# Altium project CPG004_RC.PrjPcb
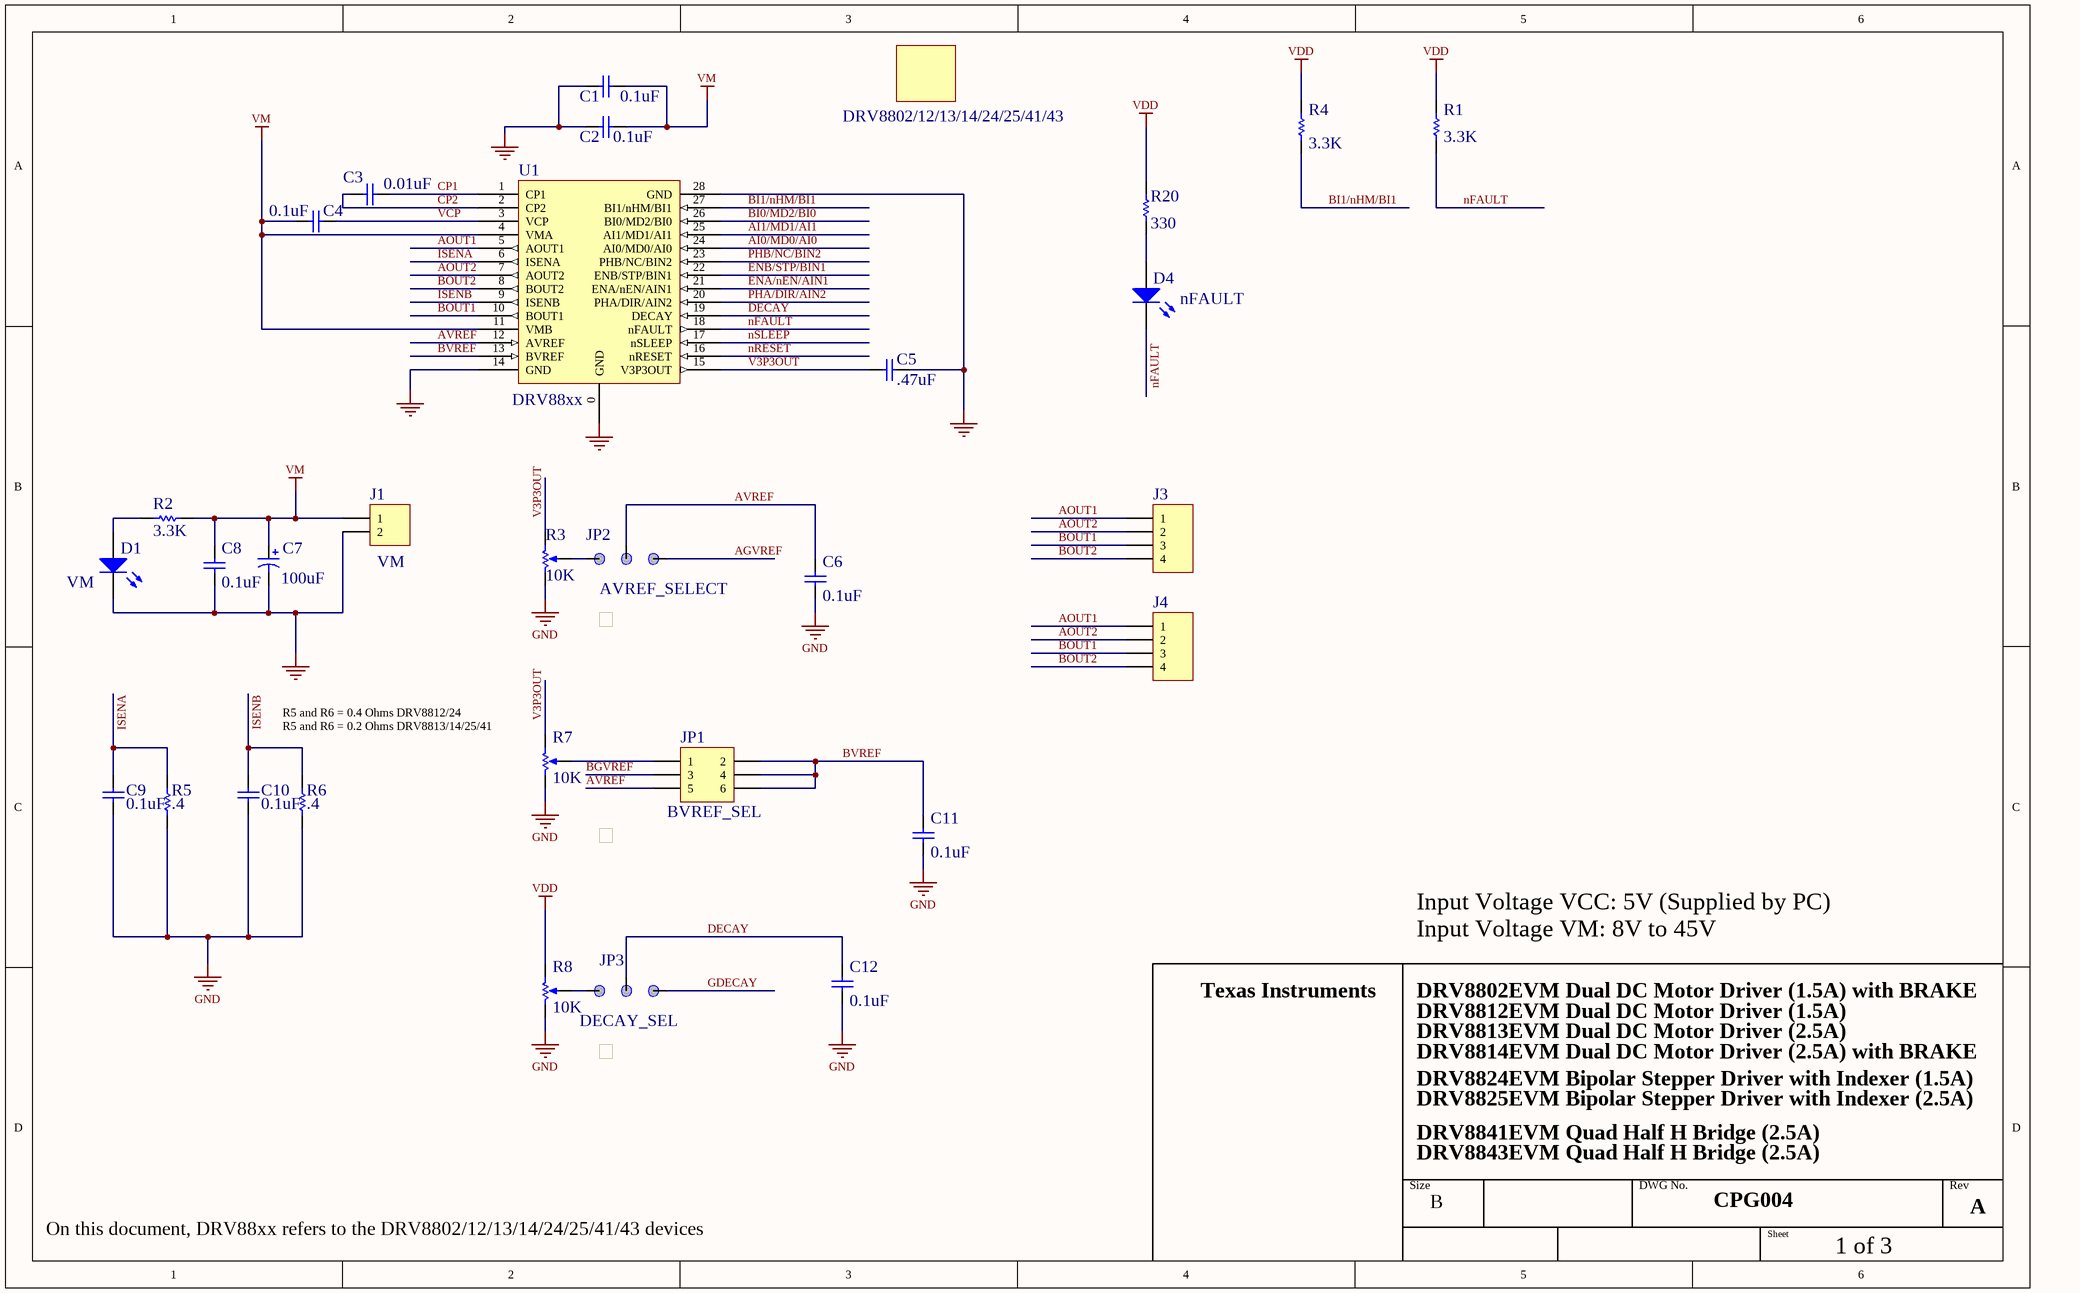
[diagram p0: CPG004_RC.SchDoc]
Title: CPG004 DRV88xx Customer Evaluation Module; ProjectFileName: CPG004 DRV8812/13/14/24/25/41 Customer EVM
3 sheets, 100 parts. Net scope: global (net labels, ports and power ports of the same name join across sheets).
Board file: CPG004_RC.PcbDoc
Sheets:
  CPG004_RC.SchDoc
  CPG004_RC_MSP430.SchDoc
  CPG004_RC_TS.SchDoc

## Sheet CPG004_RC.SchDoc: Test
size B; PageSetup: Record=PageOptions|CenterHorizontal=True|CenterVertical=True|PrintScale=0.70|XCorrection=1.00|YCorrection=1.00|PrintKind=1|BorderSize=5000000|LeftOffset=0|BottomOffset=0|Orientation=2|PaperLength=1000|PaperWidth=1000|Scale=100|PaperSource=15|PrintQuality=600|MediaType=1|DitherType=10|PaperKind=11x17|PrintScaleMode=1

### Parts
C1  value 0.1uF  [1206]
C2  value 0.1uF  [1206]
C3  0.01uF  [0805]
C4  value 0.1uF  [0805]
C5  value .47uF  [0805]
C6  value 0.1uF  [0805]
C7  value 100uF  [RB .2/.4 SS]
C8  value 0.1uF  [0805]
C9  value 0.1uF  [0805]
C10  value 0.1uF  [0805]
C11  value 0.1uF  [0805]
C12  value 0.1uF  [0805]
D1  VM  [1206_LED]
D4  nFAULT  [1206_LED]
J1  VM  [PWR_CONN2]
J3  Header 4  [PWR_CONN4]  (value not drawn)
J4  Header 4  [HDR1X4]  (value not drawn)
JP1  BVREF_SEL  [HDR2X3]
JP2  AVREF_SELECT  [JMP0.3]
JP3  DECAY_SEL  [JMP0.3]
R1  value 3.3K  [0805]
R2  value 3.3K  [0805]  (hidden comment: Res2)
R3  value 10K  [VR5]  (hidden comment: AVREF)
R4  value 3.3K  [0805]
R5  value .4  [2512]
R6  value .4  [2512]
R7  value 10K  [VR5]  (hidden comment: BVREF)
R8  value 10K  [VR5]  (hidden comment: DECAY)
R20  value 330  [0805]  (hidden comment: Res2)
SHNT1  3 pin Jumper Shunt  (value not drawn)
SHNT2  3 pin Jumper Shunt  (value not drawn)
SHNT3  3 pin Jumper Shunt  (value not drawn)
TL1  DRV8802/12/13/14/24/25/41/43  [TI LOGO]
U1  DRV88xx  [HTSSOP28 - PWP]

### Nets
GND: C1.1 C2.1 C5.1 C6.1 C7.2 C8.1 C9.1 C10.1 C11.1 C12.1 D1.2(K) J1.2 R3.3(BOT) R5.2 R6.2 R7.3(BOT) R8.3(BOT) U1.0(GND) U1.14(GND) U1.28(GND)
VDD: R1.1 R4.1 R8.1(TOP) R20.2
VM: C1.2 C2.2 C4.1 C7.1 C8.2 J1.1 R2.1 U1.4(VMA) U1.11(VMB)
AGVREF: JP2.1
AI0/MD0/AI0: U1.24(AI0/MD0/AI0)
AI1/MD1/AI1: U1.25(AI1/MD1/AI1)
AOUT1: J3.1 J4.1 U1.5(AOUT1)
AOUT2: J3.2 J4.2 U1.7(AOUT2)
AVREF: C6.2 JP1.5 JP2.2 U1.12(AVREF)
BGVREF: JP1.3
BI0/MD2/BI0: U1.26(BI0/MD2/BI0)
BI1/nHM/BI1: R4.2 U1.27(BI1/nHM/BI1)
BOUT1: J3.3 J4.3 U1.10(BOUT1)
BOUT2: J3.4 J4.4 U1.8(BOUT2)
BVREF: C11.2 JP1.2 JP1.4 JP1.6 U1.13(BVREF)
CP1: C3.1 U1.1(CP1)
CP2: C3.2 U1.2(CP2)
DECAY: C12.2 JP3.2 U1.19(DECAY)
ENA/nEN/AIN1: U1.21(ENA/nEN/AIN1)
ENB/STP/BIN1: U1.22(ENB/STP/BIN1)
GDECAY: JP3.1
ISENA: C9.2 R5.1 U1.6(ISENA)
ISENB: C10.2 R6.1 U1.9(ISENB)
nFAULT: D4.2(K) R1.2 U1.18(nFAULT)
nRESET: U1.16(nRESET)
nSLEEP: U1.17(nSLEEP)
PHA/DIR/AIN2: U1.20(PHA/DIR/AIN2)
PHB/NC/BIN2: U1.23(PHB/NC/BIN2)
V3P3OUT: C5.2 R3.1(TOP) R7.1(TOP) U1.15(V3P3OUT)
VCP: C4.2 U1.3(VCP)
NetD1_1: D1.1(A) R2.2
NetD4_1: D4.1(A) R20.1
NetJP1_1: JP1.1 R7.2(TAP)
NetJP2_3: JP2.3 R3.2(TAP)
NetJP3_3: JP3.3 R8.2(TAP)

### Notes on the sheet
- R5 and R6 = 0.4 Ohms DRV8812/24
- R5 and R6 = 0.2 Ohms DRV8813/14/25/41
- Input Voltage VCC: 5V (Supplied by PC)
- Input Voltage VM: 8V to 45V
- Texas Instruments
- DRV8812EVM Dual DC Motor Driver (1.5A)
- DRV8813EVM Dual DC Motor Driver (2.5A)
- DRV8802EVM Dual DC Motor Driver (1.5A) with BRAKE
- DRV8814EVM Dual DC Motor Driver (2.5A) with BRAKE
- DRV8824EVM Bipolar Stepper Driver with Indexer (1.5A)
- DRV8825EVM Bipolar Stepper Driver with Indexer (2.5A)
- DRV8841EVM Quad Half H Bridge (2.5A)
- DRV8843EVM Quad Half H Bridge (2.5A)
- On this document, DRV88xx refers to the DRV8802/12/13/14/24/25/41/43 devices
- Size
- B
- DWG No.
- CPG004
- Sheet
- Rev
- A
- 1 of 3

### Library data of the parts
C1 C2 = Cap: CAP .10UF 50V CERAMIC X7R 1206; Manufacturer: Kemet; Part #: 399-1248-1-ND; MFG Part Number: C1206C104M5RACTU
C3 = Cap: CAP 10000PF 50V CERAMIC X7R 0805; Manufacturer: Kemet; Part #: 399-1158-1-ND; MFG Part Number: C0805C103K5RACTU; Value: .01uF
C4 C6 C8-C12 = Cap: CAP .10UF 50V CERAMIC X7R 0805; Manufacturer: Kemet; Part #: 399-1170-1-ND; MFG Part Number: C0805C104K5RACTU
C5 = Cap: CAP CER .47UF 25V X7R 0805 FO; Manufacturer: Kemet; Part #: 399-5112-1-ND; MFG Part Number: C0805F474K3RACTU
C7 = Cap Pol1: CAP 100UF 50V ELECT M RADIAL; Part #: P5182-ND; MFG Part Number: ECA-1HM101; Manufacturer: Panasonic
D1 D4 = LED3: LED RED CLEAR 1206 SMD; MFG Part Number: HBR1105W-TR; Manufacturer: Stanley Electric & Co; Part #: 404-1033-1-ND; Value: LED RED
J1 = Header 2: TERM BLOCK 5.08MM VERT 2POS PCB; MFG Part Number: OSTTA024163; Manufacturer: On Shore Technologies; Part #: ED2580-ND; Value: Connector
J3 = Header 4: TERM BLOCK 5.08MM VERT 4POS PCB; Manufacturer: On Shore Technologies; MFG Part Number: OSTTA044163; Part #: ED2582-ND
J4 = Header 4: CONN HEADER .100 SNGL STR 4POS; Manufacturer: 3M; MFG Part Number: 929647-09-04-I; Part #: 929647-09-04-ND; Value: 4 Pos Header
JP1 = Header 3X2: CONN HEADER .100 DUAL STR 6POS; Manufacturer: 3M; MFG Part Number: 929665-09-03-I; Part #: 929665-09-03-ND; Value: 6 Pos Dual Header
JP2 JP3 = JUMPER 3 PIN: CONN HEADER .100 SINGL STR 3POS; Manufacturer: 3M; MFG Part Number: 929647-09-03-I; Part #: 929647-09-03-ND; VALUE: 3 Pos Header
R1 R4 = Res1: RES 3.3K OHM 1/8W 5% 0805 SMD; Manufacturer: Yageo; Part #: 311-3.3KARCT-ND; MFG Part Number: RC0805JR-073K3L
R2 = Res2: RES 3.3K OHM 1/8W 5% 0805 SMD; MFG Part Number: RC0805JR-073K3L; Manufacturer: Yageo; Part #: 311-3.3KARCT-ND
R3 R7 R8 = RPot: TRIMPOT CERM 10K OHM 12TRN TOP; Part #: 490-3008-ND; Manufacturer: Murata; MFG Part Number: PV37Y103C01B00
R5 R6 = Res1: RES .4OHM 2W 1% 2512 SMD; Manufacturer: Stackpole; Part #: CSRN2512FKR400CT-ND; MFG Part Number: CSRN2512FKR400
R20 = Res2: RES 330 OHM 1/8W 5% 0805 SMD; MFG Part Number: RC0805JR-07330RL; Manufacturer: Yageo; Part #: 311-330ARCT-ND
SHNT1-SHNT3 = ShuntJumper: CONN SHUNT; Manufacturer: Samtec; MFG Part Number: SNT-100-BK-T-H; Part #: SNT-100-BK-T-H-ND
TL1 = TI_LOGO: CPG004 Bare Board; Manufacturer: Texas Instruments; MFG Part Number: DRV88xx Customer EVM Bare Board; Part #: DRV8812 Customer EVM Bare Board; Value: PCB
U1 = Io_Europa: Stepper / DC Motor Driver; Manufacturer: Texas Instruments

## Sheet CPG004_RC_MSP430.SchDoc: CPG004 DRV88xx Customer Evaluation Module
size B
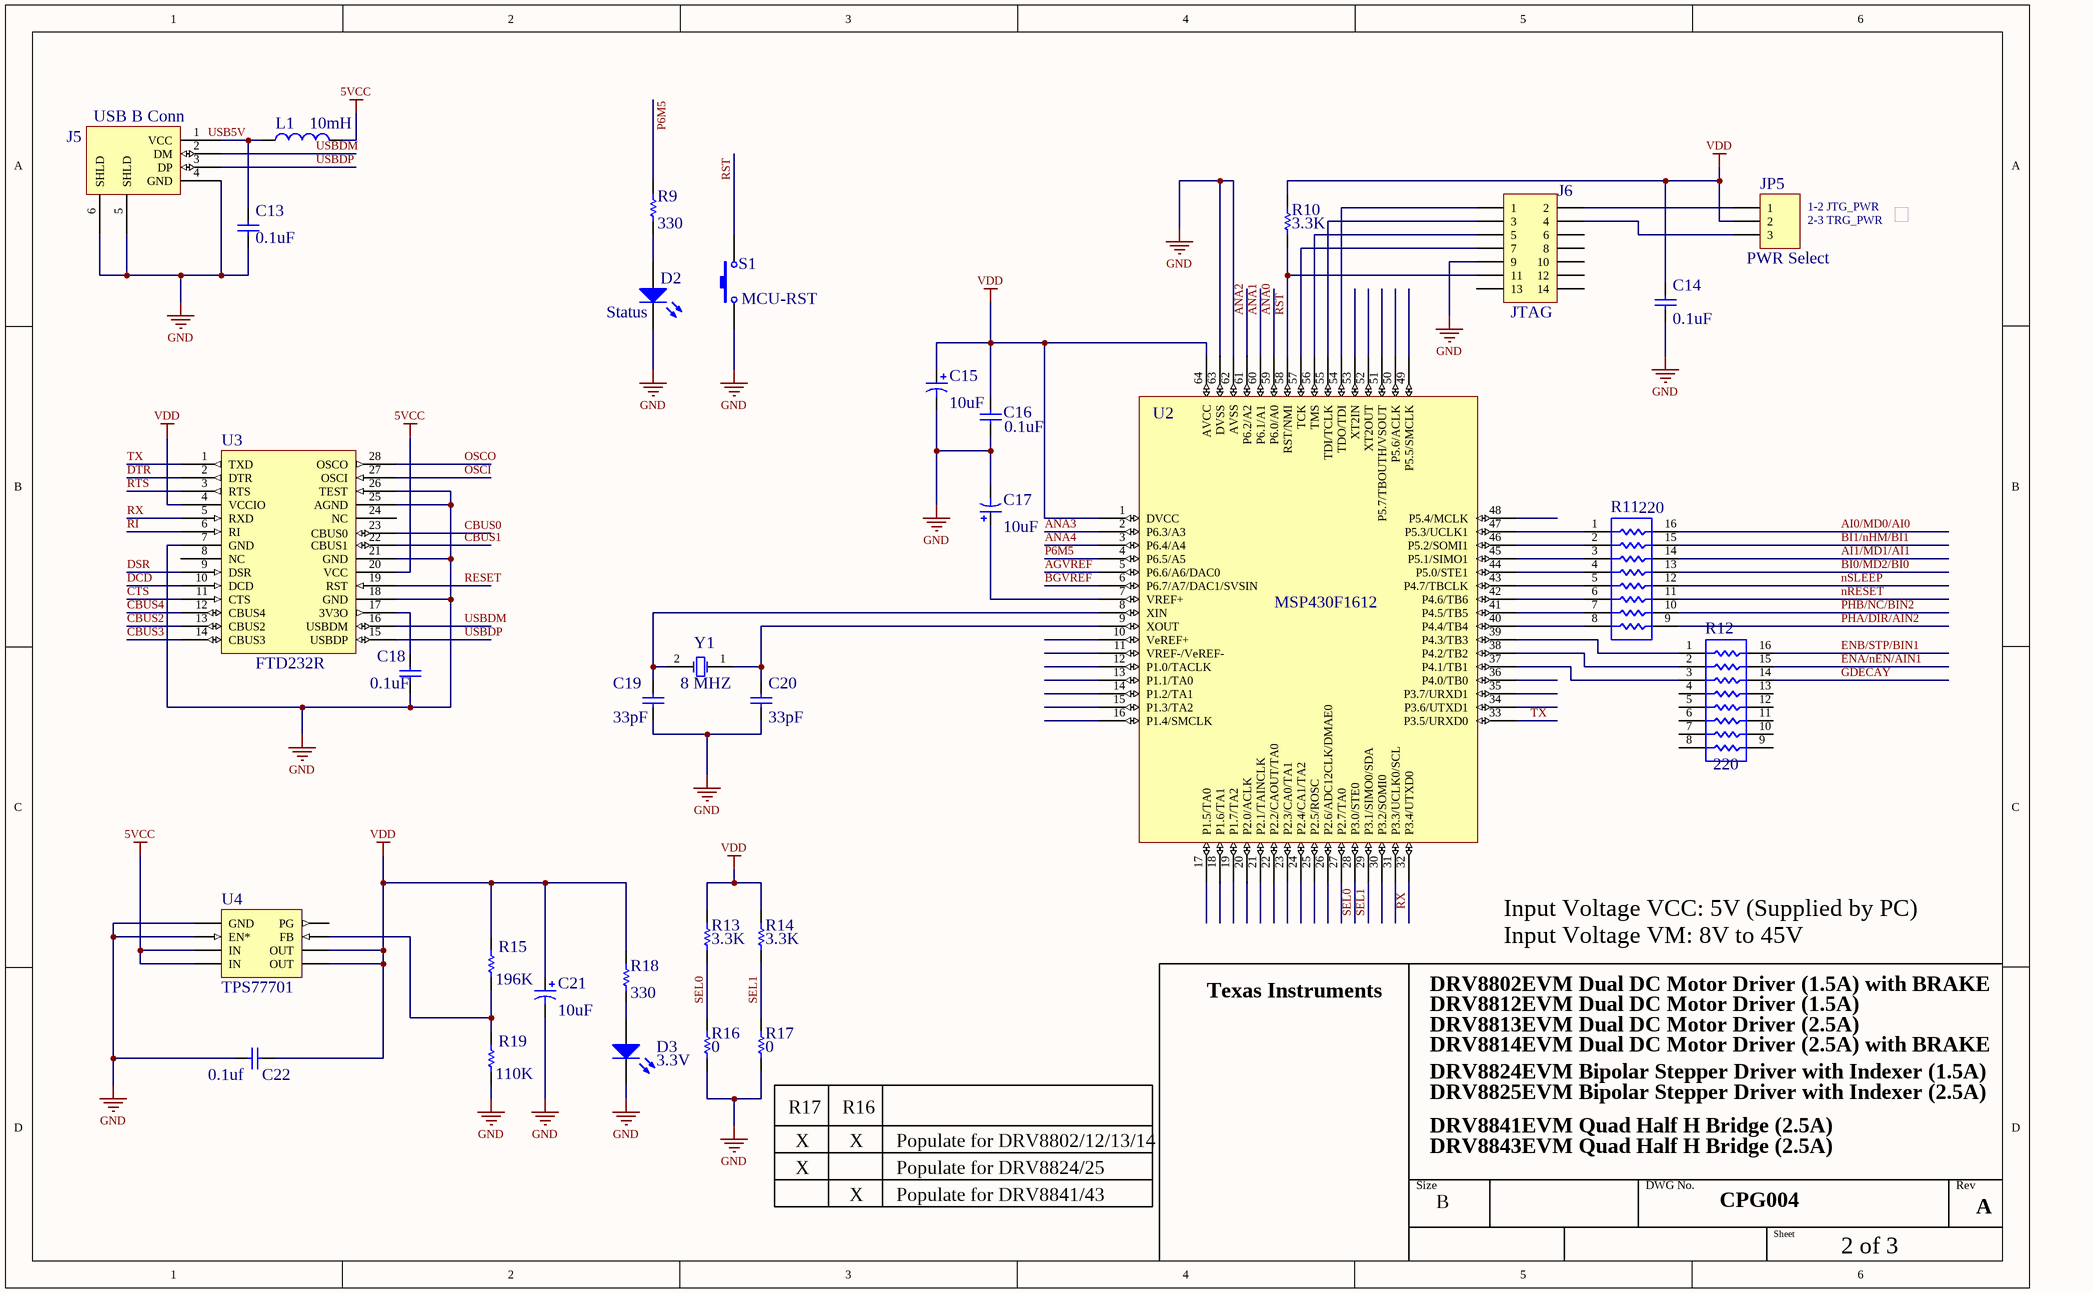
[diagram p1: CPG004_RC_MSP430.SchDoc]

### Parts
C13  value 0.1uF  [0805]  (hidden comment: Cap)
C14  value 0.1uF  [0805]  (hidden comment: Cap)
C15  value 10uF  [RB .1/.250]  (hidden comment: Cap Pol1)
C16  value 0.1uF  [0805]  (hidden comment: Cap)
C17  value 10uF  [RB .1/.250]  (hidden comment: Cap Pol1)
C18  value 0.1uF  [0805]  (hidden comment: Cap)
C19  value 33pF  [0805]  (hidden comment: Cap)
C20  value 33pF  [0805]  (hidden comment: Cap)
C21  value 10uF  [RB .1/.250]  (hidden comment: Cap Pol1)
C22  value 0.1uf  [0805]  (hidden comment: Cap1)
D2  Status  [1206_LED]
D3  3.3V  [3.5X2.8X1.9]
J5  USB B Conn  [USB_CONN]
J6  JTAG  [HDR2X7]
JP5  PWR Select  [HDR1X3]
L1  value 10mH  [0805]
R9  value 330  [0805]  (hidden comment: Res2)
R10  value 3.3K  [0805]
R11  value 220  [RES_NET_8]  (hidden comment: Res Pack3)
R12  value 220  [RES_NET_8]  (hidden comment: Res Pack3)
R13  value 3.3K  [0805]
R14  value 3.3K  [0805]
R15  value 196K  [0805]  (hidden comment: Res2)
R16  value 0  [0805]
R17  value 0  [0805]
R18  value 330  [0805]  (hidden comment: Res1)
R19  value 110K  [0805]  (hidden comment: Res2)
S1  MCU-RST  [Pana_PB]
SHNT4  3 pin Jumper Shunt  (value not drawn)
U2  MSP430F1612  [MSP430F1612]
U3  FTD232R  [FT232RL]
U4  TPS77701  [TL7726]
Y1  8 MHZ  [XTAL]

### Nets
5VCC: L1.2 U3.20(VCC) U4.3(IN) U4.4(IN)
GND: C13.1 C14.1 C15.2 C16.1 C17.2 C18.1 C19.1 C20.1 C21.2 C22.1 D2.2(K) D3.2(K) J5.4(GND) J5.5(SHLD) J5.6(SHLD) J6.9 R16.2 R17.2 R19.1 S1.1 U2.62(AVSS) U2.63(DVSS) U3.7(GND) U3.18(GND) U3.21(GND) U3.25(AGND) U3.26(TEST) U4.1(GND) U4.2(EN*)
VDD: C14.2 C15.1 C16.2 C21.1 C22.2 JP5.2 R10.1 R13.1 R14.1 R15.2 R18.2 U2.1(DVCC) U2.64(AVCC) U3.4(VCCIO) U4.5(OUT) U4.6(OUT)
AGVREF: U2.5(P6.6/A6/DAC0)
AI0/MD0/AI0: R11.16
AI1/MD1/AI1: R11.14
ANA0: U2.59(P6.0/A0)
ANA1: U2.60(P6.1/A1)
ANA2: U2.61(P6.2/A2)
ANA3: U2.2(P6.3/A3)
ANA4: U2.3(P6.4/A4)
BGVREF: U2.6(P6.7/A7/DAC1/SVSIN)
BI0/MD2/BI0: R11.13
BI1/nHM/BI1: R11.15
CBUS0: U3.23(CBUS0)
CBUS1: U3.22(CBUS1)
CBUS2: U3.13(CBUS2)
CBUS3: U3.14(CBUS3)
CBUS4: U3.12(CBUS4)
CTS: U3.11(CTS)
DCD: U3.10(DCD)
DSR: U3.9(DSR)
DTR: U3.2(DTR)
ENA/nEN/AIN1: R12.15
ENB/STP/BIN1: R12.16
GDECAY: R12.14
nRESET: R11.11
nSLEEP: R11.12
OSCI: U3.27(OSCI)
OSCO: U3.28(OSCO)
P6M5: R9.2 U2.4(P6.5/A5)
PHA/DIR/AIN2: R11.9
PHB/NC/BIN2: R11.10
RESET: U3.19(RST)
RI: U3.6(RI)
RST: J6.11 R10.2 S1.2 U2.58(RST/NMI)
RTS: U3.3(RTS)
RX: U2.32(P3.4/UTXD0) U3.5(RXD)
SEL0: R13.2 R16.1 U2.28(P3.0/STE0)
SEL1: R14.2 R17.1 U2.29(P3.1/SIMO0/SDA)
TX: U2.33(P3.5/URXD0) U3.1(TXD)
USBDM: J5.2(DM) U3.16(USBDM)
USBDP: J5.3(DP) U3.15(USBDP)
NetC13_2: C13.2 J5.1(VCC) L1.1
NetC17_1: C17.1 U2.7(VREF+)
NetC18_2: C18.2 U3.17(3V3O)
NetC19_2: C19.2 U2.8(XIN) Y1.2(OSC2)
NetC20_2: C20.2 U2.9(XOUT) Y1.1(OSC1)
NetD2_1: D2.1(A) R9.1
NetD3_1: D3.1(A) R18.1
NetJ6_1: J6.1 U2.54(TDO/TDI)
NetJ6_2: J6.2 JP5.1
NetJ6_3: J6.3 U2.55(TDI/TCLK)
NetJ6_4: J6.4 JP5.3
NetJ6_5: J6.5 U2.56(TMS)
NetJ6_7: J6.7 U2.57(TCK)
NetR11_1: R11.1 U2.47(P5.3/UCLK1)
NetR11_2: R11.2 U2.46(P5.2/SOMI1)
NetR11_3: R11.3 U2.45(P5.1/SIMO1)
NetR11_4: R11.4 U2.44(P5.0/STE1)
NetR11_5: R11.5 U2.43(P4.7/TBCLK)
NetR11_6: R11.6 U2.42(P4.6/TB6)
NetR11_7: R11.7 U2.41(P4.5/TB5)
NetR11_8: R11.8 U2.40(P4.4/TB4)
NetR12_1: R12.1 U2.39(P4.3/TB3)
NetR12_2: R12.2 U2.38(P4.2/TB2)
NetR12_3: R12.3 U2.37(P4.1/TB1)
NetR15_1: R15.1 R19.2 U4.7(FB)

Not connected (* = marked no-connect by the designer): J6 6 8 10 12 13 14; R12 4 5 6 7 8 9 10 11 12 13; U2 10(VeREF+) 11(VREF-/VeREF-) 12(P1.0/TACLK) 13(P1.1/TA0) 14(P1.2/TA1) 15(P1.3/TA2) 16(P1.4/SMCLK) 17(P1.5/TA0) 18(P1.6/TA1) 19(P1.7/TA2) 20(P2.0/ACLK) 21(P2.1/TAINCLK) 22(P2.2/CAOUT/TA0) 23(P2.3/CA0/TA1) 24(P2.4/CA1/TA2) 25(P2.5/ROSC) 26(P2.6/ADC12CLK/DMAE0) 27(P2.7/TA0) 30(P3.2/SOMI0) 31(P3.3/UCLK0/SCL) 34(P3.6/UTXD1) 35(P3.7/URXD1) 36(P4.0/TB0) 48(P5.4/MCLK) 49(P5.5/SMCLK) 50(P5.6/ACLK) 51(P5.7/TBOUTH/VSOUT) 52(XT2OUT) 53(XT2IN); U3 8(NC) 24(NC); U4 8(PG)

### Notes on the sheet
- (near SHNT4) 1-2 JTG_PWR
- (near SHNT4) 2-3 TRG_PWR
- Input Voltage VCC: 5V (Supplied by PC)
- Input Voltage VM: 8V to 45V
- Texas Instruments
- DRV8812EVM Dual DC Motor Driver (1.5A)
- DRV8813EVM Dual DC Motor Driver (2.5A)
- DRV8802EVM Dual DC Motor Driver (1.5A) with BRAKE
- DRV8814EVM Dual DC Motor Driver (2.5A) with BRAKE
- DRV8824EVM Bipolar Stepper Driver with Indexer (1.5A)
- DRV8825EVM Bipolar Stepper Driver with Indexer (2.5A)
- (near R17) R17
- X
- R16
- Populate for DRV8802/12/13/14
- Populate for DRV8824/25
- DRV8841EVM Quad Half H Bridge (2.5A)
- DRV8843EVM Quad Half H Bridge (2.5A)
- Populate for DRV8841/43
- Size
- B
- DWG No.
- CPG004
- Sheet
- Rev
- A
- 2 of 3
- Labels drawn without touching a wire or pin: USB5V

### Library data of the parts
C13 C14 C16 C18 = Cap: CAP .10UF 50V CERAMIC X7R 0805; MFG Part Number: C0805C104K5RACTU; Manufacturer: Kemet; Part #: 399-1170-1-ND
C15 C17 C21 = Cap Pol1: CAP 10UF 25V ELECT VR RADIAL; MFG Part Number: UVR1E100MDD; Manufacturer: Nichicon; Part #: 493-1057-ND
C19 C20 = Cap: CAP CERAMIC 33PF 50V NP0 0805; MFG Part Number: CC0805JRNP09BN330; Manufacturer: Yageo; Part #: 311-1105-1-ND
C22 = Cap1: CAP .10UF 50V CERAMIC X7R 0805; MFG Part Number: C0805C104K5RACTU; Manufacturer: Kemet; Part #: 399-1170-1-ND
D2 = LED3: as D1 on sheet CPG004_RC
D3 = LED3: LED RED CLEAR 1206 SMD; Manufacturer: Stanley; MFG Part Number: HBR1105W-TR; Part #: 404-1033-1-ND; Value: LED RED
J5 = USB_B_CONN: CONN USB RT ANG RECPT TYPE B BLK; MFG Part Number: 67068-8000; Manufacturer: Molex; Part #: WM17113-ND; Value: USB B
J6 = Header 7X2H: CONN HEADER .100 DUAL STR 14POS; MFG Part Number: 929665-09-07-I; Manufacturer: 3M; Part #: 929665-09-07-ND; Value: 14 Pos Header
JP5 = Header 3: CONN HEADER .100 SINGL STR 3POS; MFG Part Number: 929647-09-03-I; Manufacturer: 3M; Part #: 929647-09-03-ND; Value: 3 Pos Header
L1 = Inductor: FERRITE 1.5A 40 OHM 0805 SMD; MFG Part Number: MI0805K400R-10; Manufacturer: Steward; Part #: 240-2389-1-ND
R9 = Res2: as R20 on sheet CPG004_RC
R10 R13 R14 = Res1: as R1 on sheet CPG004_RC
R11 R12 = Res Pack3: RES NET 8RES 220 OHM 16PIN SMD; Manufacturer: CTS Resistors; MFG Part Number: 766163221GP; Part #: 766-163-R220P-ND
R15 = Res2: RES 196K OHM 1/8W 1% 0805 SMD; MFG Part Number: RC0805FR-07196KL; Manufacturer: Yageo; Part #: 311-196KCRCT-ND
R16 R17 = Res1: RES 0.0 OHM 1/8W 5% 0805 SMD; Manufacturer: Yageo; Part #: 311-0.0ARCT-ND; MFG Part Number: RC0805JR-070RL
R18 = Res1: RES 330 OHM 1/8W 5% 0805 SMD; Manufacturer: Yageo; MFG Part Number: RC0805JR-07330RL; Part #: 311-330ARCT-ND
R19 = Res2: RES 110K OHM 1/8W 5% 0805 SMD; MFG Part Number: RC0805JR-07110KL; Manufacturer: Yageo; Part #: 311-110KARCT-ND
S1 = SW-PB: SWITCH LIGHT TOUCH 4.3MM 100GF; MFG Part Number: EVQ-11A04M; Manufacturer: Panasonic; Part #: P8070SCT-ND; Value: Push Button
SHNT4 = ShuntJumper: as SHNT1 on sheet CPG004_RC
U2 = MSP430F1612: IC MCU 16BIT 55K FLASH 64-LQFP; MFG Part Number: MSP430F1612IPM; Manufacturer: Texas Instruments; Part #: 296-17885-ND; Value: MSP430 MCU
U3 = FT232R: IC USB TO SERIAL UART 28-SSOP; MFG Part Number: FT232RL R; Manufacturer: FTDI; Part #: 768-1007-1-ND; Value: USB Driver
U4 = TPS77701: IC ADJ 750MA LDO REG 8-SOIC; MFG Part Number: TPS77701D; Manufacturer: Texas Instruments; Part #: 296-2783-5-ND
Y1 = XTAL: CRYSTAL 8.00 MHZ 20PF 49US; MFG Part Number: ECS-80-20-4; Manufacturer: ECS Inc.; Part #: X165-ND

## Sheet CPG004_RC_TS.SchDoc: CPG004 DRV88xx Customer Evaluation Module
size A
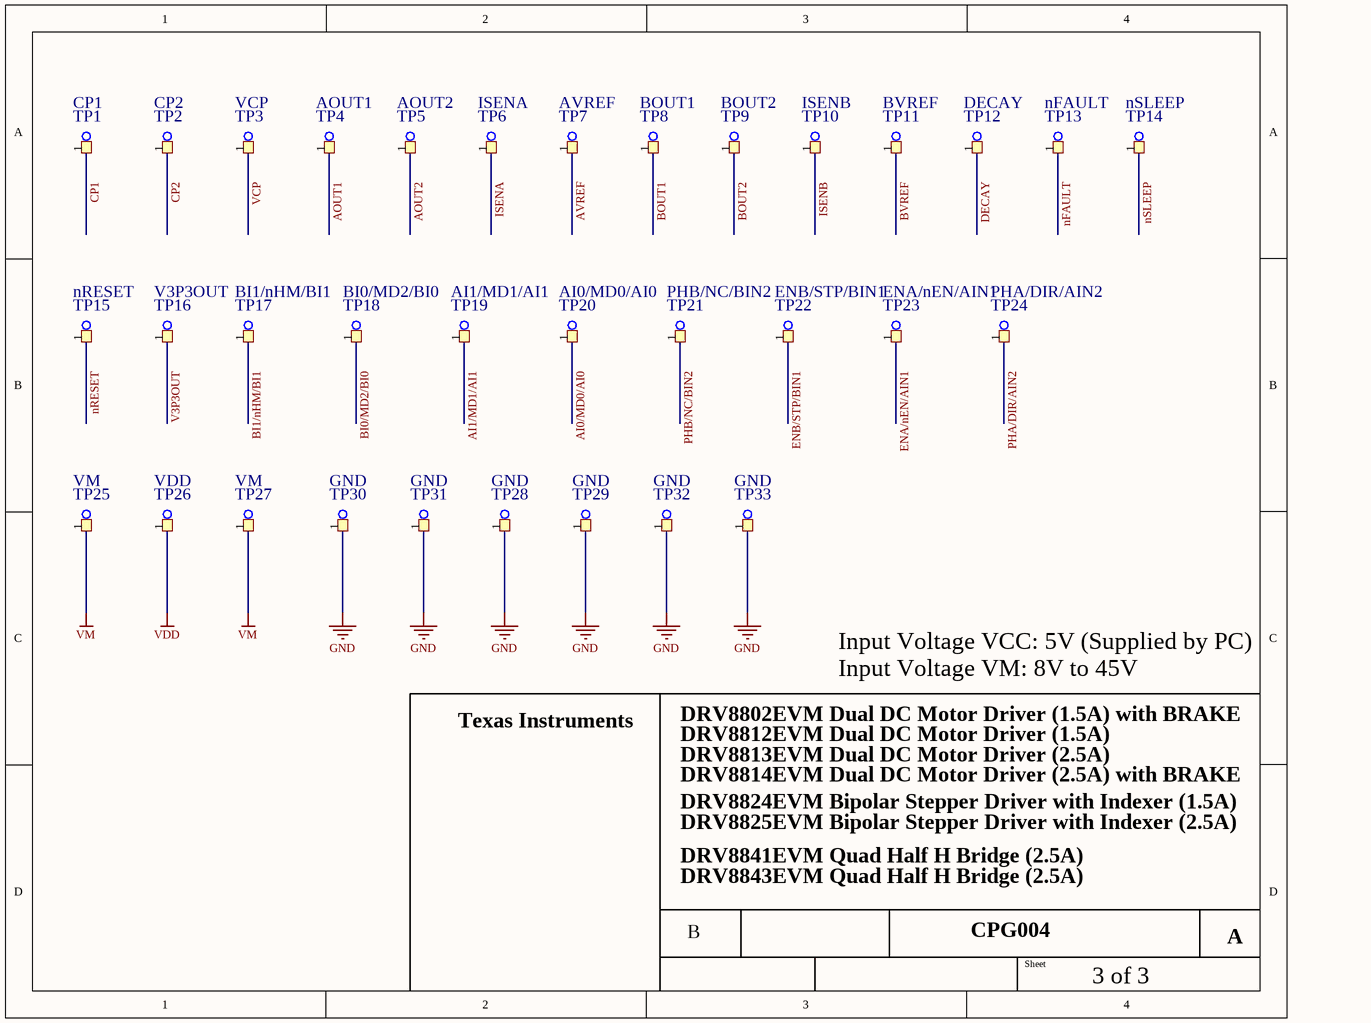
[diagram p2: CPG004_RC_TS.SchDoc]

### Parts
TP1  CP1  [TEST POINT 0.052]
TP2  CP2  [TEST POINT 0.052]
TP3  VCP  [TEST POINT 0.052]
TP4  AOUT1  [TEST POINT 0.052]
TP5  AOUT2  [TEST POINT 0.052]
TP6  ISENA  [TEST POINT 0.052]
TP7  AVREF  [TEST POINT 0.052]
TP8  BOUT1  [TEST POINT 0.052]
TP9  BOUT2  [TEST POINT 0.052]
TP10  ISENB  [TEST POINT 0.052]
TP11  BVREF  [TEST POINT 0.052]
TP12  DECAY  [TEST POINT 0.052]
TP13  nFAULT  [TEST POINT 0.052]
TP14  nSLEEP  [TEST POINT 0.052]
TP15  nRESET  [TEST POINT 0.052]
TP16  V3P3OUT  [TEST POINT 0.052]
TP17  BI1/nHM/BI1  [TEST POINT 0.052]
TP18  BI0/MD2/BI0  [TEST POINT 0.052]
TP19  AI1/MD1/AI1  [TEST POINT 0.052]
TP20  AI0/MD0/AI0  [TEST POINT 0.052]
TP21  PHB/NC/BIN2  [TEST POINT 0.052]
TP22  ENB/STP/BIN1  [TEST POINT 0.052]
TP23  ENA/nEN/AIN1  [TEST POINT 0.052]
TP24  PHA/DIR/AIN2  [TEST POINT 0.052]
TP25  VM  [TEST POINT 0.052]
TP26  VDD  [TEST POINT 0.052]
TP27  VM  [TEST POINT 0.052]
TP28  GND  [TEST POINT 0.052]
TP29  GND  [TEST POINT 0.052]
TP30  GND  [TEST POINT 0.052]
TP31  GND  [TEST POINT 0.052]
TP32  GND  [TEST POINT 0.052]
TP33  GND  [TEST POINT 0.052]

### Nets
GND: TP28.1 TP29.1 TP30.1 TP31.1 TP32.1 TP33.1
VDD: TP26.1
VM: TP25.1 TP27.1
AI0/MD0/AI0: TP20.1
AI1/MD1/AI1: TP19.1
AOUT1: TP4.1
AOUT2: TP5.1
AVREF: TP7.1
BI0/MD2/BI0: TP18.1
BI1/nHM/BI1: TP17.1
BOUT1: TP8.1
BOUT2: TP9.1
BVREF: TP11.1
CP1: TP1.1
CP2: TP2.1
DECAY: TP12.1
ENA/nEN/AIN1: TP23.1
ENB/STP/BIN1: TP22.1
ISENA: TP6.1
ISENB: TP10.1
nFAULT: TP13.1
nRESET: TP15.1
nSLEEP: TP14.1
PHA/DIR/AIN2: TP24.1
PHB/NC/BIN2: TP21.1
V3P3OUT: TP16.1
VCP: TP3.1

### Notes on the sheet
- Input Voltage VCC: 5V (Supplied by PC)
- Input Voltage VM: 8V to 45V
- Texas Instruments
- DRV8812EVM Dual DC Motor Driver (1.5A)
- DRV8813EVM Dual DC Motor Driver (2.5A)
- DRV8802EVM Dual DC Motor Driver (1.5A) with BRAKE
- DRV8814EVM Dual DC Motor Driver (2.5A) with BRAKE
- DRV8824EVM Bipolar Stepper Driver with Indexer (1.5A)
- DRV8825EVM Bipolar Stepper Driver with Indexer (2.5A)
- DRV8841EVM Quad Half H Bridge (2.5A)
- DRV8843EVM Quad Half H Bridge (2.5A)
- B
- CPG004
- Sheet
- A
- 3 of 3

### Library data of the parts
TP1-TP24 = TEST POINT: Test Points LG WHT TERM; Manufacturer: Kobiconn; MFG Part Number: 151-101-RC; Part #: 151-101-RC (white) Mouser; Value: WHITE
TP25-TP27 = TEST POINT: Test Points LG RED TERM; Manufacturer: Kobiconn; MFG Part Number: 151-107-RC; Part #: 151-107-RC (red) Mouser
TP28-TP33 = TEST POINT: Test Points LG BLACK TERM; Manufacturer: Kobiconn; MFG Part Number: 151-103-RC; Part #: 151-103-RC (Black) Mouser

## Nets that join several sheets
GND: CPG004_RC (20 pins), CPG004_RC_MSP430 (29 pins), CPG004_RC_TS (6 pins)
VDD: CPG004_RC (R1.1 R4.1 R8.1 R20.2), CPG004_RC_MSP430 (16 pins), CPG004_RC_TS (TP26.1)
VM: CPG004_RC (9 pins), CPG004_RC_TS (TP25.1 TP27.1)
AGVREF: CPG004_RC (JP2.1), CPG004_RC_MSP430 (U2.5)
AI0/MD0/AI0: CPG004_RC (U1.24), CPG004_RC_MSP430 (R11.16), CPG004_RC_TS (TP20.1)
AI1/MD1/AI1: CPG004_RC (U1.25), CPG004_RC_MSP430 (R11.14), CPG004_RC_TS (TP19.1)
AOUT1: CPG004_RC (J3.1 J4.1 U1.5), CPG004_RC_TS (TP4.1)
AOUT2: CPG004_RC (J3.2 J4.2 U1.7), CPG004_RC_TS (TP5.1)
AVREF: CPG004_RC (C6.2 JP1.5 JP2.2 U1.12), CPG004_RC_TS (TP7.1)
BGVREF: CPG004_RC (JP1.3), CPG004_RC_MSP430 (U2.6)
BI0/MD2/BI0: CPG004_RC (U1.26), CPG004_RC_MSP430 (R11.13), CPG004_RC_TS (TP18.1)
BI1/nHM/BI1: CPG004_RC (R4.2 U1.27), CPG004_RC_MSP430 (R11.15), CPG004_RC_TS (TP17.1)
BOUT1: CPG004_RC (J3.3 J4.3 U1.10), CPG004_RC_TS (TP8.1)
BOUT2: CPG004_RC (J3.4 J4.4 U1.8), CPG004_RC_TS (TP9.1)
BVREF: CPG004_RC (5 pins), CPG004_RC_TS (TP11.1)
CP1: CPG004_RC (C3.1 U1.1), CPG004_RC_TS (TP1.1)
CP2: CPG004_RC (C3.2 U1.2), CPG004_RC_TS (TP2.1)
DECAY: CPG004_RC (C12.2 JP3.2 U1.19), CPG004_RC_TS (TP12.1)
ENA/nEN/AIN1: CPG004_RC (U1.21), CPG004_RC_MSP430 (R12.15), CPG004_RC_TS (TP23.1)
ENB/STP/BIN1: CPG004_RC (U1.22), CPG004_RC_MSP430 (R12.16), CPG004_RC_TS (TP22.1)
GDECAY: CPG004_RC (JP3.1), CPG004_RC_MSP430 (R12.14)
ISENA: CPG004_RC (C9.2 R5.1 U1.6), CPG004_RC_TS (TP6.1)
ISENB: CPG004_RC (C10.2 R6.1 U1.9), CPG004_RC_TS (TP10.1)
nFAULT: CPG004_RC (D4.2 R1.2 U1.18), CPG004_RC_TS (TP13.1)
nRESET: CPG004_RC (U1.16), CPG004_RC_MSP430 (R11.11), CPG004_RC_TS (TP15.1)
nSLEEP: CPG004_RC (U1.17), CPG004_RC_MSP430 (R11.12), CPG004_RC_TS (TP14.1)
PHA/DIR/AIN2: CPG004_RC (U1.20), CPG004_RC_MSP430 (R11.9), CPG004_RC_TS (TP24.1)
PHB/NC/BIN2: CPG004_RC (U1.23), CPG004_RC_MSP430 (R11.10), CPG004_RC_TS (TP21.1)
V3P3OUT: CPG004_RC (C5.2 R3.1 R7.1 U1.15), CPG004_RC_TS (TP16.1)
VCP: CPG004_RC (C4.2 U1.3), CPG004_RC_TS (TP3.1)

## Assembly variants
CPG004-001 DRV8812: all parts fitted
CPG004-007 DRV8802: all parts fitted
CPG004-003 DRV8813: all parts fitted
CPG004-004 DRV8814: all parts fitted
CPG004-002 DRV8824: not fitted R16
CPG004-005 DRV8825: not fitted R16
CPG004-006 DRV8841: not fitted R17
CPG004-008 DRV8843: not fitted R17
